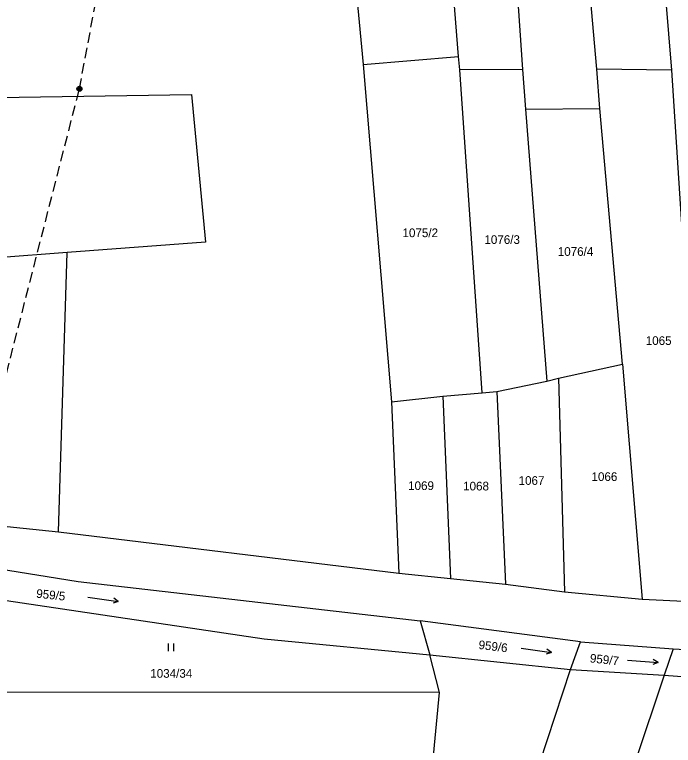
# Model space of a CAD drawing. Extents: x -820420 to -815896, y -1105820 to -1103643.
# Drawn here: x -818260.8 to -818131.9, y -1104579.4 to -1104436.5 of the extents above; entities that cross this region are included whole.
import ezdxf
from ezdxf.enums import TextEntityAlignment as Align

# ---------------------------------------------------------------- set-up
doc = ezdxf.new("R2010")
doc.units = 0
doc.header["$LTSCALE"] = 0.68
doc.linetypes.add('MEDIUM_DASHED', pattern=[4.5, 3, -1.5])
for name, color, linetype, lineweight in [('1', 7, 'Continuous', 25), ('3', 7, 'Continuous', 25), ('6', 7, 'Continuous', 25)]:
    doc.layers.add(name, color=color, linetype=linetype, lineweight=lineweight)
doc.layers.add('2', color=7, linetype='Continuous')

msp = doc.modelspace()

# ---------------------------------------------------------------- linework, layer by layer
at = {"layer": '1'}
for p, q in [((-818146.86, -1104447.19), (-818156.72, -1104335.39)), ((-818173.93, -1104444.72), (-818182.25, -1104340.39)), ((-818202.07, -1104343.83), (-818192.57, -1104446.32)), ((-818134.4, -1104422.03), (-818132.24, -1104447.37)), ((-818192.57, -1104446.32), (-818173.93, -1104444.72)), ((-818173.67, -1104447.36), (-818173.93, -1104444.72)), ((-818192.57, -1104446.32), (-818187.03, -1104512.25)), ((-818161.43, -1104447.24), (-818173.67, -1104447.36)), ((-818169.3, -1104510.49), (-818173.67, -1104447.36)), ((-818161.43, -1104447.24), (-818160.83, -1104455.02)), ((-818132.24, -1104447.37), (-818146.86, -1104447.19)), ((-818146.25, -1104454.91), (-818146.86, -1104447.19)), ((-818132.24, -1104447.37), (-818129.11, -1104495.63)), ((-818301.21, -1104453.37), (-818226.13, -1104452.14)), ((-818226.13, -1104452.14), (-818223.43, -1104481.02)), ((-818160.83, -1104455.02), (-818146.25, -1104454.91)), ((-818160.83, -1104455.02), (-818156.64, -1104508.19)), ((-818141.84, -1104504.89), (-818146.25, -1104454.91)), ((-818223.43, -1104481.02), (-818250.48, -1104483.05)), ((-818250.48, -1104483.05), (-818300.75, -1104486.83)), ((-818252.18, -1104537.64), (-818250.48, -1104483.05)), ((-818154.36, -1104507.62), (-818141.84, -1104504.89)), ((-818141.84, -1104504.89), (-818137.98, -1104550.8)), ((-818166.42, -1104510.23), (-818156.64, -1104508.19)), ((-818156.64, -1104508.19), (-818154.36, -1104507.62)), ((-818154.36, -1104507.62), (-818153.2, -1104549.41)), ((-818169.3, -1104510.49), (-818166.42, -1104510.23)), ((-818166.42, -1104510.23), (-818164.75, -1104547.91)), ((-818187.03, -1104512.25), (-818177, -1104511.14)), ((-818177, -1104511.14), (-818169.3, -1104510.49)), ((-818177, -1104511.14), (-818175.46, -1104546.76)), ((-818187.03, -1104512.25), (-818185.59, -1104545.75)), ((-818271.24, -1104535.73), (-818252.18, -1104537.64)), ((-818252.18, -1104537.64), (-818185.59, -1104545.75)), ((-818288.7, -1104540.87), (-818248.29, -1104547.36)), ((-818185.59, -1104545.75), (-818175.46, -1104546.76)), ((-818248.29, -1104547.36), (-818181.44, -1104555.03)), ((-818175.46, -1104546.76), (-818164.75, -1104547.91)), ((-818283.33, -1104547.98), (-818211.91, -1104558.58)), ((-818164.75, -1104547.91), (-818153.2, -1104549.41)), ((-818153.2, -1104549.41), (-818137.98, -1104550.8)), ((-818137.98, -1104550.8), (-818125.55, -1104551.46)), ((-818181.44, -1104555.03), (-818179.52, -1104561.71)), ((-818150.03, -1104559.18), (-818181.44, -1104555.03)), ((-818211.91, -1104558.58), (-818179.52, -1104561.71)), ((-818152, -1104564.59), (-818150.03, -1104559.18)), ((-818150.03, -1104559.18), (-818131.94, -1104560.55)), ((-818179.52, -1104561.71), (-818152, -1104564.59)), ((-818177.63, -1104569.05), (-818179.52, -1104561.71)), ((-818131.94, -1104560.55), (-818133.7, -1104565.65)), ((-818131.94, -1104560.55), (-818100.61, -1104562.13)), ((-818174.88, -1104634.05), (-818152, -1104564.59)), ((-818152, -1104564.59), (-818133.7, -1104565.65)), ((-818133.7, -1104565.65), (-818159.92, -1104643.63)), ((-818133.7, -1104565.65), (-818102.69, -1104568.1)), ((-818177.63, -1104569.05), (-818271.4, -1104568.99)), ((-818178.97, -1104583.19), (-818177.63, -1104569.05))]:
    msp.add_line(p, q, dxfattribs=at)
msp.add_lwpolyline([(-818182.25, -1104340.39), (-818168.91, -1104337.62), (-818161.43, -1104447.24)], dxfattribs=at)
at = {"layer": '3'}
for p, q in [((-818240.463, -1104551.258), (-818241.501, -1104551.619)), ((-818230.621, -1104560.98), (-818230.621, -1104559.48)), ((-818229.62, -1104560.98), (-818229.62, -1104559.48)), ((-818155.713, -1104561.228), (-818156.751, -1104561.589)), ((-818134.891, -1104563.169), (-818135.901, -1104563.601))]:
    msp.add_line(p, q, dxfattribs=at)
for points in [[(-818246.405, -1104550.423), (-818240.463, -1104551.258), (-818241.361, -1104550.626)], [(-818161.655, -1104560.393), (-818155.713, -1104561.228), (-818156.611, -1104560.596)], [(-818140.876, -1104562.75), (-818134.891, -1104563.169), (-818135.831, -1104562.601)]]:
    msp.add_lwpolyline(points, dxfattribs=at)
at = {"layer": '6', "linetype": 'MEDIUM_DASHED'}
msp.add_lwpolyline([(-818269.18, -1104533.35), (-818248.07, -1104451.05), (-818232.5, -1104368.04)], dxfattribs=at)
at = {"layer": '6'}
for radius in [0.5, 0.4, 0.3, 0.2, 0.1]:
    msp.add_circle((-818248.0734, -1104451.0499), radius, dxfattribs=at)

# ---------------------------------------------------------------- texts
at = {"layer": '2'}
for s, p in [('1075/2', (-818181.4, -1104480.045)), ('1076/3', (-818165.38, -1104481.375)), ('1076/4', (-818151.03, -1104483.705)), ('1065', (-818134.77, -1104501.125)), ('1066', (-818145.38, -1104527.715)), ('1067', (-818159.64, -1104528.475)), ('1069', (-818181.25, -1104529.485)), ('1068', (-818170.49, -1104529.565)), ('1034/34', (-818230.109, -1104566.185))]:
    msp.add_text(s, height=1.7, dxfattribs=at).set_placement(p, align=Align.CENTER)
for s, rotation, p in [('959/5', 354, (-818253.7583, -1104550.8172)), ('959/6', 353, (-818167.2581, -1104560.8781)), ('959/7', 354, (-818145.4583, -1104563.4772))]:
    msp.add_text(s, height=1.7, rotation=rotation, dxfattribs=at).set_placement(p, align=Align.CENTER)

doc.saveas('drawing.dxf')
